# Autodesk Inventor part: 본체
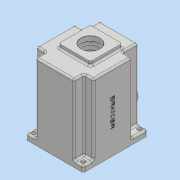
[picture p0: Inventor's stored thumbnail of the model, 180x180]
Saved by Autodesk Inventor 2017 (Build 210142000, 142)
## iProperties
Part Number: 본체
Material: 일반
Document SubType Name: Modeling
Designer: MRC
Density: 1 g/cm^3
Appearance: 기본값
Author: MRC
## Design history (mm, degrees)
sketch "스케치1"
  geometry: L1 (-49, 60)-(49, 60); L2 (49, 60)-(49, -50); L3 (49, -50)-(-49, -50); L4 (-49, -50)-(-49, 60); L5 (-49, 60)-(49, -50); L6 (49, 60)-(-49, -50); 3 further points
  constraints: 12 end point, 3 midpoint, 2 parallel, 1 horizontal, 1 perpendicular, 1 vertical alignment
  dimensions: "d1" = 50 distance from line of L3 point (0, 0); "d2" = 110 distance of L3.end L1.start; "d3" = 98 distance of L2.end L3.end
extrude "돌출1" new body sketch "스케치1" distance "d4" = 10; taper "d5" = 0 deg
sketch "스케치2"
  geometry: L1 (49, 60)-(-49, 60) reference; L2 (-49, -50)-(49, -50) reference; L3 (49, -50)-(49, 60) reference; L4 (-33, -50)-(33, -50); L5 (33, -50)-(33, 60); L6 (33, 60)-(-33, 60); L7 (-33, 60)-(-33, -50); L8 (-33, -50)-(33, 60); L9 (33, -50)-(-33, 60); L10 (-49, -33)-(49, -33); L11 (49, -33)-(49, 33); L12 (49, 33)-(-49, 33); L13 (-49, 33)-(-49, -33); L14 (-49, -33)-(49, 33); L15 (49, -33)-(-49, 33); 6 further points
  constraints: 24 end point, 7 midpoint, 4 parallel, 2 collinear, 2 horizontal, 2 perpendicular, 2 vertical alignment, 1 point on line
  dimensions: "d6" = 66 distance between parallel lines of L5 L7; "d7" = 27 distance between parallel lines of L1 L12; "d8" = 17 distance between parallel lines of L2 L10
extrude "돌출2" join sketch "스케치2" distance "d9" = 120; taper "d10" = 0 deg
sketch "스케치3"
  geometry: L1 (-27, -16)-(27, -16); L2 (27, -16)-(27, 38); L3 (27, 38)-(-27, 38); L4 (-27, 38)-(-27, -16); L5 (-27, -16)-(27, 38); L6 (27, -16)-(-27, 38); 3 further points
  constraints: 12 end point, 3 midpoint, 2 parallel, 1 horizontal, 1 perpendicular, 1 vertical alignment
  dimensions: "d11" = 11 distance of point (0, 0) point (0, 11); "d12" = 54 distance of L2.end L3.end; "d13" = 54 distance of L1.end L2.end
extrude "돌출3" join sketch "스케치3" distance "d14" = 7; taper "d15" = 0 deg
sketch "스케치4"
  geometry: L1 (0, 0)-(98, 0) reference; C1 r 22.5 at (49, -40); 2 further points
  constraints: 1 centre point, 1 midpoint, 1 vertical alignment
  dimensions: "d16" = 40 distance from line of L1 C1.centre; "d19" = 45 diameter of C1
extrude "돌출4" join sketch "스케치4" distance "d20" = 10; taper "d21" = 0 deg
sketch "스케치5"
  geometry: L1 (0, 0)-(98, 0) reference; C1 r 15 at (49, -89); 2 further points
  constraints: 1 centre point, 1 midpoint, 1 vertical alignment
  dimensions: "d22" = 89 distance from line of C1.centre L1; "d23" = 30 diameter of C1
extrude "돌출5" join sketch "스케치5" distance "d24" = 5; taper "d25" = 0 deg
sketch "스케치6"
  geometry: L1 (-23, 35.143)-(-23, 50); L2 (-23, 50)-(23, 50); L3 (23, 50)-(23, 35.143); A1 r 42 centre (0, 0) between (23, 35.143) and (-23, 35.143); 2 further points
  constraints: 6 end point, 2 perpendicular, 2 point on circle, 1 centre point, 1 coincident, 1 midpoint, 1 vertical, 1 vertical alignment
  dimensions: "d26" = 84 diameter of A1; "d27" = 46 distance between parallel lines of L3 L1; "d28" = 50 distance from line of point (0, 0) L2
extrude "돌출6" cut sketch "스케치6" distance "d29" = 121; taper "d30" = 0 deg
sketch "스케치7"
  geometry: L1 (-23, 35.143)-(-23, 50) reference; L2 (-23, 50)-(23, 50) reference; L3 (23, 50)-(23, 35.143) reference; L4 (-26, 36.729)-(-26, 53); L5 (-26, 53)-(26, 53); L6 (26, 53)-(26, 36.729); A1 r 42 centre (0, 0) between (-23, 35.143) and (23, 35.143) reference; A2 r 45 centre (0, 0) between (-26, 36.729) and (26, 36.729)
  constraints: 6 end point, 2 point on circle, 1 centre point, 3 other
  dimensions: "d31" = 3 distance between parallel lines of L5 L2
extrude "돌출7" cut sketch "스케치7" distance "d32" = 9; taper "d33" = 0 deg
sketch "스케치8"
  geometry: C1 r 21 at (0, 11); C2 r 15 at (0, -20); A1 r 42 centre (0, 0) between (-23, 35.143) and (23, 35.143) reference
  constraints: 2 centre point, 2 vertical alignment
  dimensions: "d34" = 42 diameter of C1; "d35" = 30 diameter of C2; "d36" = 11 distance of A1.centre C1.centre; "d37" = 20 distance of A1.centre C2.centre
extrude "돌출8" join sketch "스케치8" distance "d38" = 7; taper "d39" = 0 deg
hole "구멍1" diameter "d42" = 19; stored, may be unused: countersink angle "d46" = 90 deg, drill point angle "d48" = 0 deg; dims "d40" = 10, "d41" = 10, "d43" = 6, "d44" = 22, "d45" = 7, "d47" = 10
hole "구멍2" diameter "d51" = 28; stored, may be unused: countersink angle "d55" = 90 deg, drill point angle "d57" = 0 deg; dims "d49" = 10, "d50" = 10, "d52" = 6, "d53" = 35, "d54" = 10, "d56" = 50
sketch "스케치9"
  geometry: C1 r 14 at (0, 11) reference; C2 r 16 at (0, 11); 1 further point
  constraints: 1 centre point, 1 coincident
  dimensions: "d58" = 32 diameter of C2
extrude "돌출9" cut sketch "스케치9" distance "d59" = 8.3; taper "d60" = 0 deg
sketch "스케치10"
  geometry: C1 r 15 at (0, 0) reference; C2 r 10 at (0, 0); 1 further point
  constraints: 1 centre point, 1 coincident
  dimensions: "d61" = 20 diameter of C2
extrude "돌출10" cut sketch "스케치10" distance "d62" = 38.8; taper "d63" = 0 deg
sketch "스케치11"
  geometry: C1 r 10 at (23, -32) reference; C2 r 15 at (23, -32); 1 further point
  constraints: 1 centre point, 1 coincident
  dimensions: "d64" = 30 diameter of C2
extrude "돌출11" cut sketch "스케치11" distance "d65" = 5; taper "d66" = 0 deg
hole "구멍3" diameter "d69" = 33.376; stored, may be unused: countersink angle "d73" = 90 deg, drill point angle "d75" = 0 deg; dims "d67" = 10, "d68" = 10, "d70" = 30, "d71" = 35, "d72" = 10, "d74" = 30
sketch "스케치12"
  geometry: L1 (-36, 4)-(-41.809, 4); L2 (-36, -4)-(-41.809, -4); A1 r 42 centre (0, 0) between (-23, 35.143) and (23, 35.143) reference; A2 r 4 centre (-36, 0) between (-36, 4) and (-36, -4)
  constraints: 4 end point, 4 point on circle, 2 tangent, 1 centre point, 1 horizontal, 1 horizontal alignment, 1 parallel
  dimensions: "d76" = 36 distance of A1.centre A2.centre; "d77" = 8 diameter of A2
extrude "돌출12" join sketch "스케치12" stored distance "d78" = 5; taper "d79" = 0 deg
hole "구멍4" diameter "d82" = 3.242; stored, may be unused: countersink angle "d86" = 90 deg, drill point angle "d88" = 118 deg; dims "d83" = 7, "d84" = 35, "d85" = 10, "d87" = 9, "d89" = 10, "d90" = 10
fillet "모깎기1" dims "d91" = 6, "d92" = 3
fillet "모깎기2" dims "d93" = 3
fillet "모깎기3" dims "d94" = 3
fillet "모깎기4" dims "d95" = 3
fillet "모깎기5" dims "d96" = 3
sketch "스케치13"
  geometry: L1 (-49, 57)-(-49, -47) reference; L2 (-46, -50)-(46, -50) reference; C1 r 3.5 at (-42, -43)
  constraints: 1 centre point
  dimensions: "d97" = 7 diameter of C1; "d98" = 7 distance from line of L1 C1.centre; "d99" = 7 distance from line of L2 C1.centre
extrude "돌출13" cut sketch "스케치13" distance "d100" = 10; taper "d101" = 0 deg
chamfer "모따기1" distance "d108" = 1; stored, may be unused: second distance "d109" = 2, angle "d110" = 45 deg
chamfer "모따기2" distance "d111" = 0.8; stored, may be unused: second distance "d112" = 2, angle "d113" = 30 deg
fillet "모깎기6" dims "d114" = 0.3
fillet "모깎기7" dims "d115" = 3
sketch "스케치14"
  geometry: L1 (-130, 104)-(-130, 83) reference; 2 further points
  constraints: 1 horizontal alignment, 1 other
  dimensions: "d116" = 65 distance from line of point (-65, 47) L1
feature "엠보싱1" sketch "스케치14" dims "d117" = 0.5, "d118" = 0
chamfer "모따기3" distance "d119" = 1; stored, may be unused: second distance "d120" = 2, angle "d121" = 45 deg
node "솔리드1"
mirror "미러1"
pattern_linear "직사각형 패턴1" dims "d104" = 84, "d107" = 96
